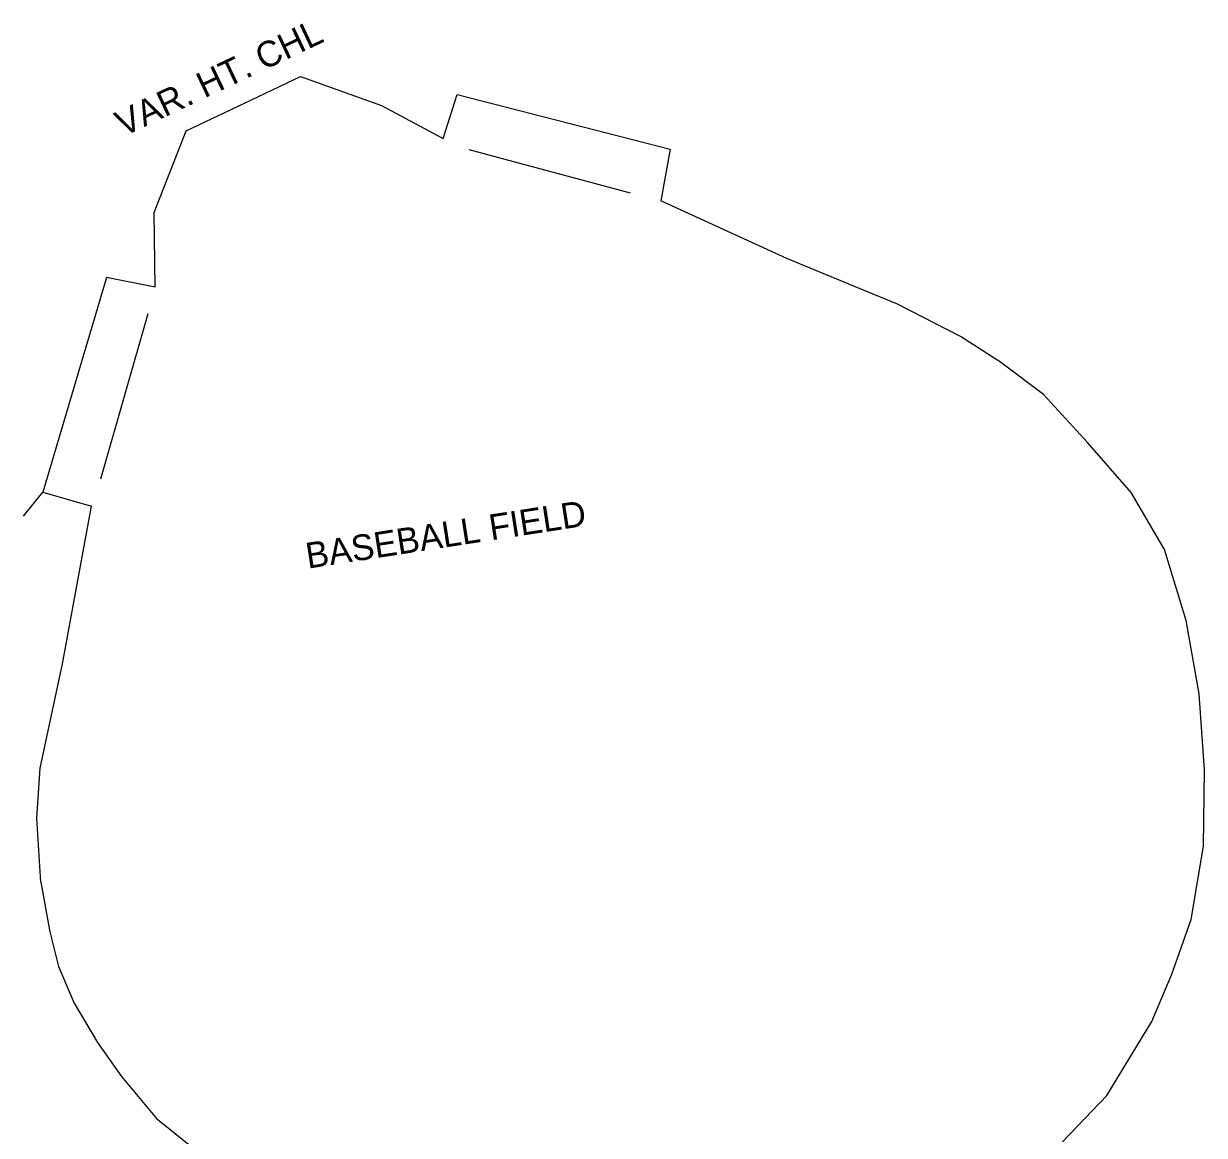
# Model space of a CAD drawing. Extents: x 1645945 to 2447332, y 713118 to 970361.
# Drawn here: x 1647155.4 to 1647293.1, y 969385.1 to 969514.7 of the extents above; entities that cross this region are included whole.
import ezdxf

# ---------------------------------------------------------------- set-up
doc = ezdxf.new("R2010")
doc.units = 0
for name, color, linetype in [('Exist Other Culture Area Outline', 7, 'Continuous'), ('Exist Other Culture Area Outline Text', 7, 'Continuous'), ('Exist Other Culture Fence Line', 7, 'Continuous'), ('Exist Other Culture Fence Line Text', 7, 'Continuous')]:
    doc.layers.add(name, color=color, linetype=linetype)

msp = doc.modelspace()

# ---------------------------------------------------------------- linework, layer by layer
at = {"layer": 'Exist Other Culture Area Outline'}
msp.add_line((1647244.41, 969487.35), (1647229.7, 969494.08), dxfattribs=at)
for points in [[(1647276.54, 969384.33), (1647281.72, 969389.72), (1647286.98, 969398.36), (1647289.29, 969403.86), (1647291.58, 969410.26), (1647292.99, 969418.81), (1647293.1, 969427.72), (1647292.51, 969436.57), (1647290.96, 969445.13), (1647288.46, 969453.39), (1647284.55, 969460.04), (1647279.47, 969465.9), (1647274.35, 969471.48), (1647269.34, 969475.25), (1647264.65, 969478.24), (1647257.32, 969482.02), (1647247.57, 969486.04), (1647244.41, 969487.35)], [(1647157.39, 969414.6), (1647156.91, 969422.09), (1647157.3, 969427.89), (1647159.91, 969440.06), (1647163.3, 969458.45)], [(1647157.39, 969414.6), (1647158.44, 969408.8), (1647159.43, 969404.75), (1647161.28, 969400.51), (1647163.99, 969395.92), (1647166.79, 969391.93), (1647170.89, 969387.03), (1647177.41, 969381.81)]]:
    msp.add_lwpolyline(points, dxfattribs=at)
at = {"layer": 'Exist Other Culture Fence Line'}
for p, q in [((1647207.29, 969500.05), (1647226.11, 969495)), ((1647164.38, 969461.66), (1647169.92, 969480.95)), ((1647155.38, 969457.3), (1647157.61, 969460.09))]:
    msp.add_line(p, q, dxfattribs=at)
for points in [[(1647170.73, 969484), (1647170.6, 969492.7), (1647174.35, 969502.24), (1647181.13, 969505.45), (1647187.67, 969508.57), (1647197.11, 969505.19), (1647204.3, 969501.35), (1647205.93, 969506.48), (1647230.79, 969500.11), (1647229.7, 969494.08)], [(1647170.73, 969484), (1647165.05, 969485.14), (1647157.61, 969460.09), (1647163.3, 969458.45)]]:
    msp.add_lwpolyline(points, dxfattribs=at)

# ---------------------------------------------------------------- texts
at = {"layer": 'Exist Other Culture Area Outline Text'}
msp.add_text('BASEBALL FIELD', height=3, rotation=8.7749, dxfattribs=at).set_placement((1647188.53, 969451.17))
at = {"layer": 'Exist Other Culture Fence Line Text'}
msp.add_text('VAR. HT. CHL', height=3, rotation=25.352, dxfattribs=at).set_placement((1647167, 969501.52))

doc.saveas('drawing.dxf')
